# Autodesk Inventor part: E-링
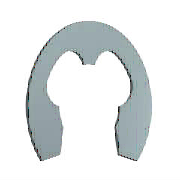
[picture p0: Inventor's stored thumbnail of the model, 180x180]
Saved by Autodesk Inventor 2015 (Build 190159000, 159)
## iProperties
IsCustomPart: 1
Created: 2012-02
Part Number: E-링
Material: 강철, 연강
Description: 일반용 테이퍼 및 줄어든 횡단면 리테이닝 링 - E-링 외부 시리즈 3CM1 리테이닝 링
Document SubType Name: Modeling
Standard: ANSI B27.7
Designer: mduedu
Standard Revision: 1999
Standards Organization: ANSI
Language: ko-KR
Size Designation: 6
Categories: <MemberInstance><Categories><Category DisplayName="샤프트 부품" InternalName="7f7aeb1f-a693-4053-b835-cee3144e0d98" Mnemonic="SHFT"><Category DisplayName="써클립" Inter
Density: 7.85 g/cm^3
Appearance: 기본값
Mass: 0.225854 g
Surface Area: 1.26477 cm^2
Volume: 0.0287712 cm^3
Author: mduedu
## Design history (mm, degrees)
sketch "스케치1"
  geometry: L1 (-0.485, 0.024)-(0, 0.024) reference; L2 (-3.206, 0)-(3.486, 0) reference; L3 (-2.223, -3.946)-(2.223, -3.946); L4 (0, 1.949)-(0, -3.479) reference; L5 (-2.91, -2.006)-(-2.435, -2.006); L6 (-0.485, -0.066)-(-0.485, 0.405); L7 (0, 2.574)-(2.53, 2.574); L8 (-2.223, -3.946)-(-3.022, -6.291); L9 (0, -0.551)-(-1.278, -0.551); L10 (2.223, -3.946)-(3.022, -6.291); L11 (2.91, -2.006)-(2.435, -2.006); L12 (0.485, -0.066)-(0.485, 0.405); C1 r 3 at (0, -2.976); A1 r 2.425 centre (0, -2.976) between (-2.297, -2.199) and (-2.223, -3.946); A2 r 0.485 centre (0, -0.066) between (-0.485, -0.066) and (0.485, -0.066); A3 r 5.55 centre (0, -2.976) between (4.27, -6.521) and (-4.27, -6.521); A4 r 3.88 centre (0, -2.976) between (-0.97, 0.78) and (-3.424, -1.15); A5 r 0.388 centre (-0.873, 0.405) between (-0.485, 0.405) and (-0.97, 0.78); A6 r 0.582 centre (-2.91, -1.424) between (-3.424, -1.15) and (-2.91, -2.006); A7 r 0.145 centre (-2.435, -2.152) between (-2.297, -2.199) and (-2.435, -2.006); A8 r 0.727 centre (-3.711, -6.057) between (-4.27, -6.521) and (-3.022, -6.291); A9 r 0.727 centre (3.711, -6.057) between (3.022, -6.291) and (4.27, -6.521); A10 r 2.425 centre (0, -2.976) between (2.223, -3.946) and (2.297, -2.199); A11 r 0.145 centre (2.435, -2.152) between (2.435, -2.006) and (2.297, -2.199); A12 r 0.582 centre (2.91, -1.424) between (2.91, -2.006) and (3.424, -1.15); A13 r 3.88 centre (0, -2.976) between (3.424, -1.15) and (0.97, 0.78); A14 r 0.388 centre (0.873, 0.405) between (0.97, 0.78) and (0.485, 0.405); 1 further point
  constraints: 30 point on circle, 20 end point, 15 centre point, 13 symmetric about line, 12 tangent, 8 point on line, 4 parallel, 2 coincident, 2 horizontal, 1 concentric, 1 perpendicular, 1 vertical alignment, 9 other
  dimensions: "d0" = 6 diameter of C1 (= WD); "d3" = 0.97 distance from line of A1.centre L3 (= 0.2 x ND); "d4" = 0.485 radius of A2 (= 0.1 x ND); "d5" = 11.1 diameter of A3 (= SD2); "d8" = 3.88 radius of A4 (= 0.8 x ND); "d9" = 0.97 distance from line of A1.centre L5 (= 0.2 x ND); "d10" = 0.388 radius of A5 (= 0.08 x ND); "d11" = 0.582 radius of A6 (= 0.12 x ND); "d12" = 0.1455 radius of A7 (= 0.03 x ND); "d13" = 0.7275 radius of A8 (= 0.15 x ND); "d14" = 2.425 distance from line of A1.centre L9 (= 0.5 x ND); "d15" = 2.425 radius of A1 (= 0.5 x ND)
extrude "본체" new body sketch "스케치1" distance "d16" = 0.6 (= SD); taper "d17" = 0 deg
workaxis "Work Axis1"
workaxis "Work Axis2"
workplane "Work Plane1"
body "Solid1"
other parameters: "ND" = 4.85 [user parameter; used in 14 equation terms], "SD" = 0.6 [user parameter; used in 1 equation term], "WD" = 6 (= WDMIN) [user parameter; used in 1 equation term], "d1" = 7.76 (= 1.6 x ND), "d2" = 4.85 (= ND), "SD2" = 11.1 [user parameter; used in 1 equation term], "d6" = 4.85 (= ND), "d7" = 0.7275 (= 0.15 x ND), "d18" = 0, "d19" = 0, "d27" = 0, "d28" = 0, "WDMIN" = 6 [user parameter; used in 1 equation term], "SNB" = 0.7 [user parameter], "WDMAX" = 7 [user parameter], "BUBRMI" = 1.2 [user parameter]
